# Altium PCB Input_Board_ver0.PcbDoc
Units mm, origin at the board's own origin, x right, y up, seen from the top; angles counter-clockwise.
Board outline 80 x 80 mm, 4 copper layers (Component Side, Signal Layer 1, Signal Layer 2, Bottom Layer), stack 0.651 mm thick; 143 components, 54 nets, 312 pads, 266 vias.
Unrouted connection lines stored in the file: 326.
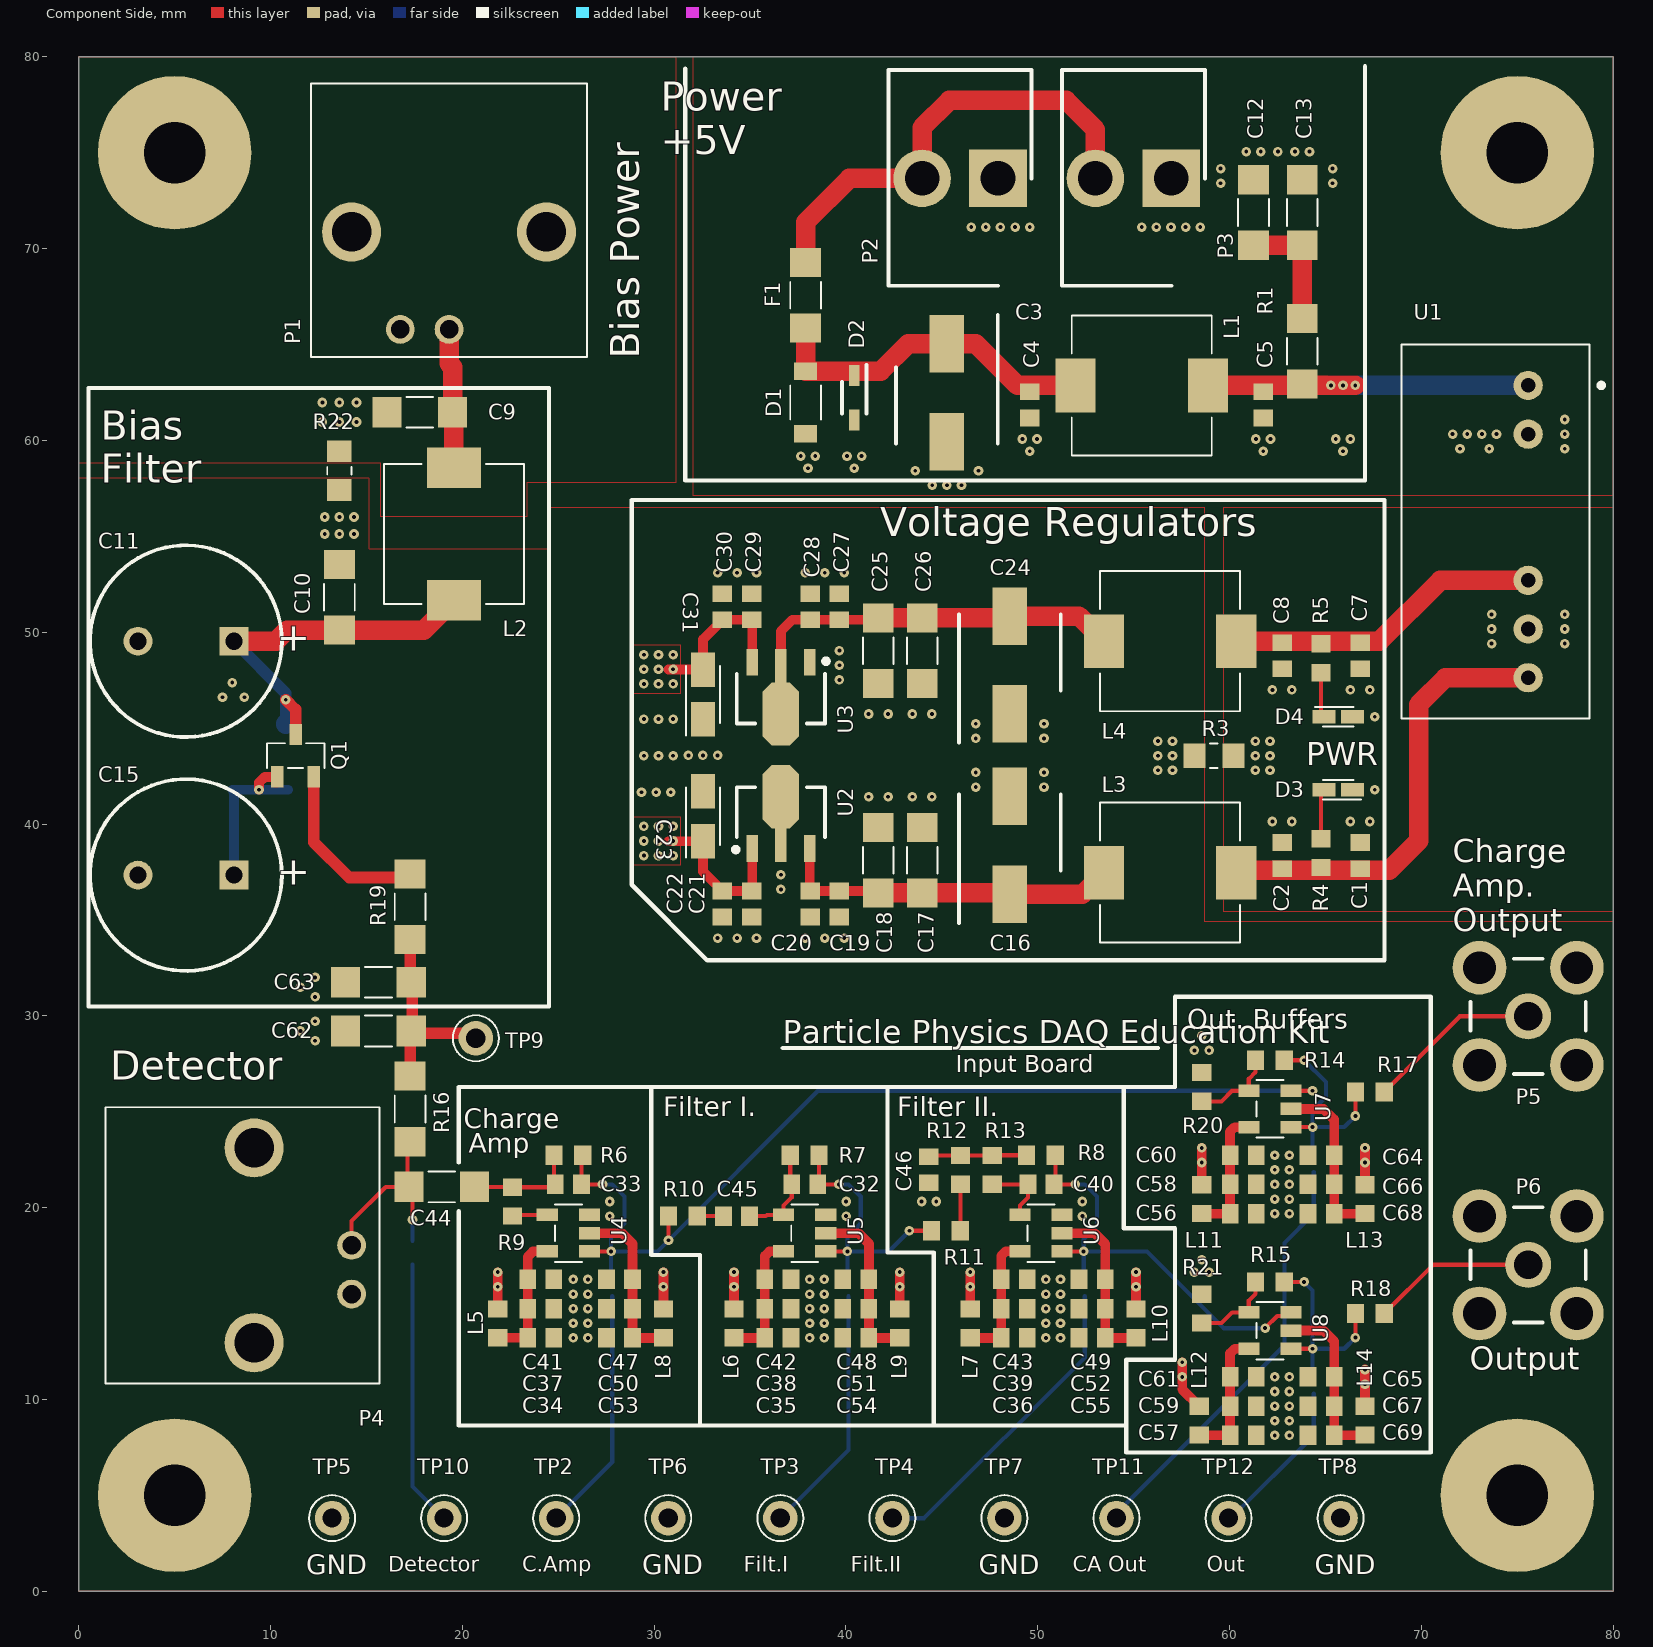
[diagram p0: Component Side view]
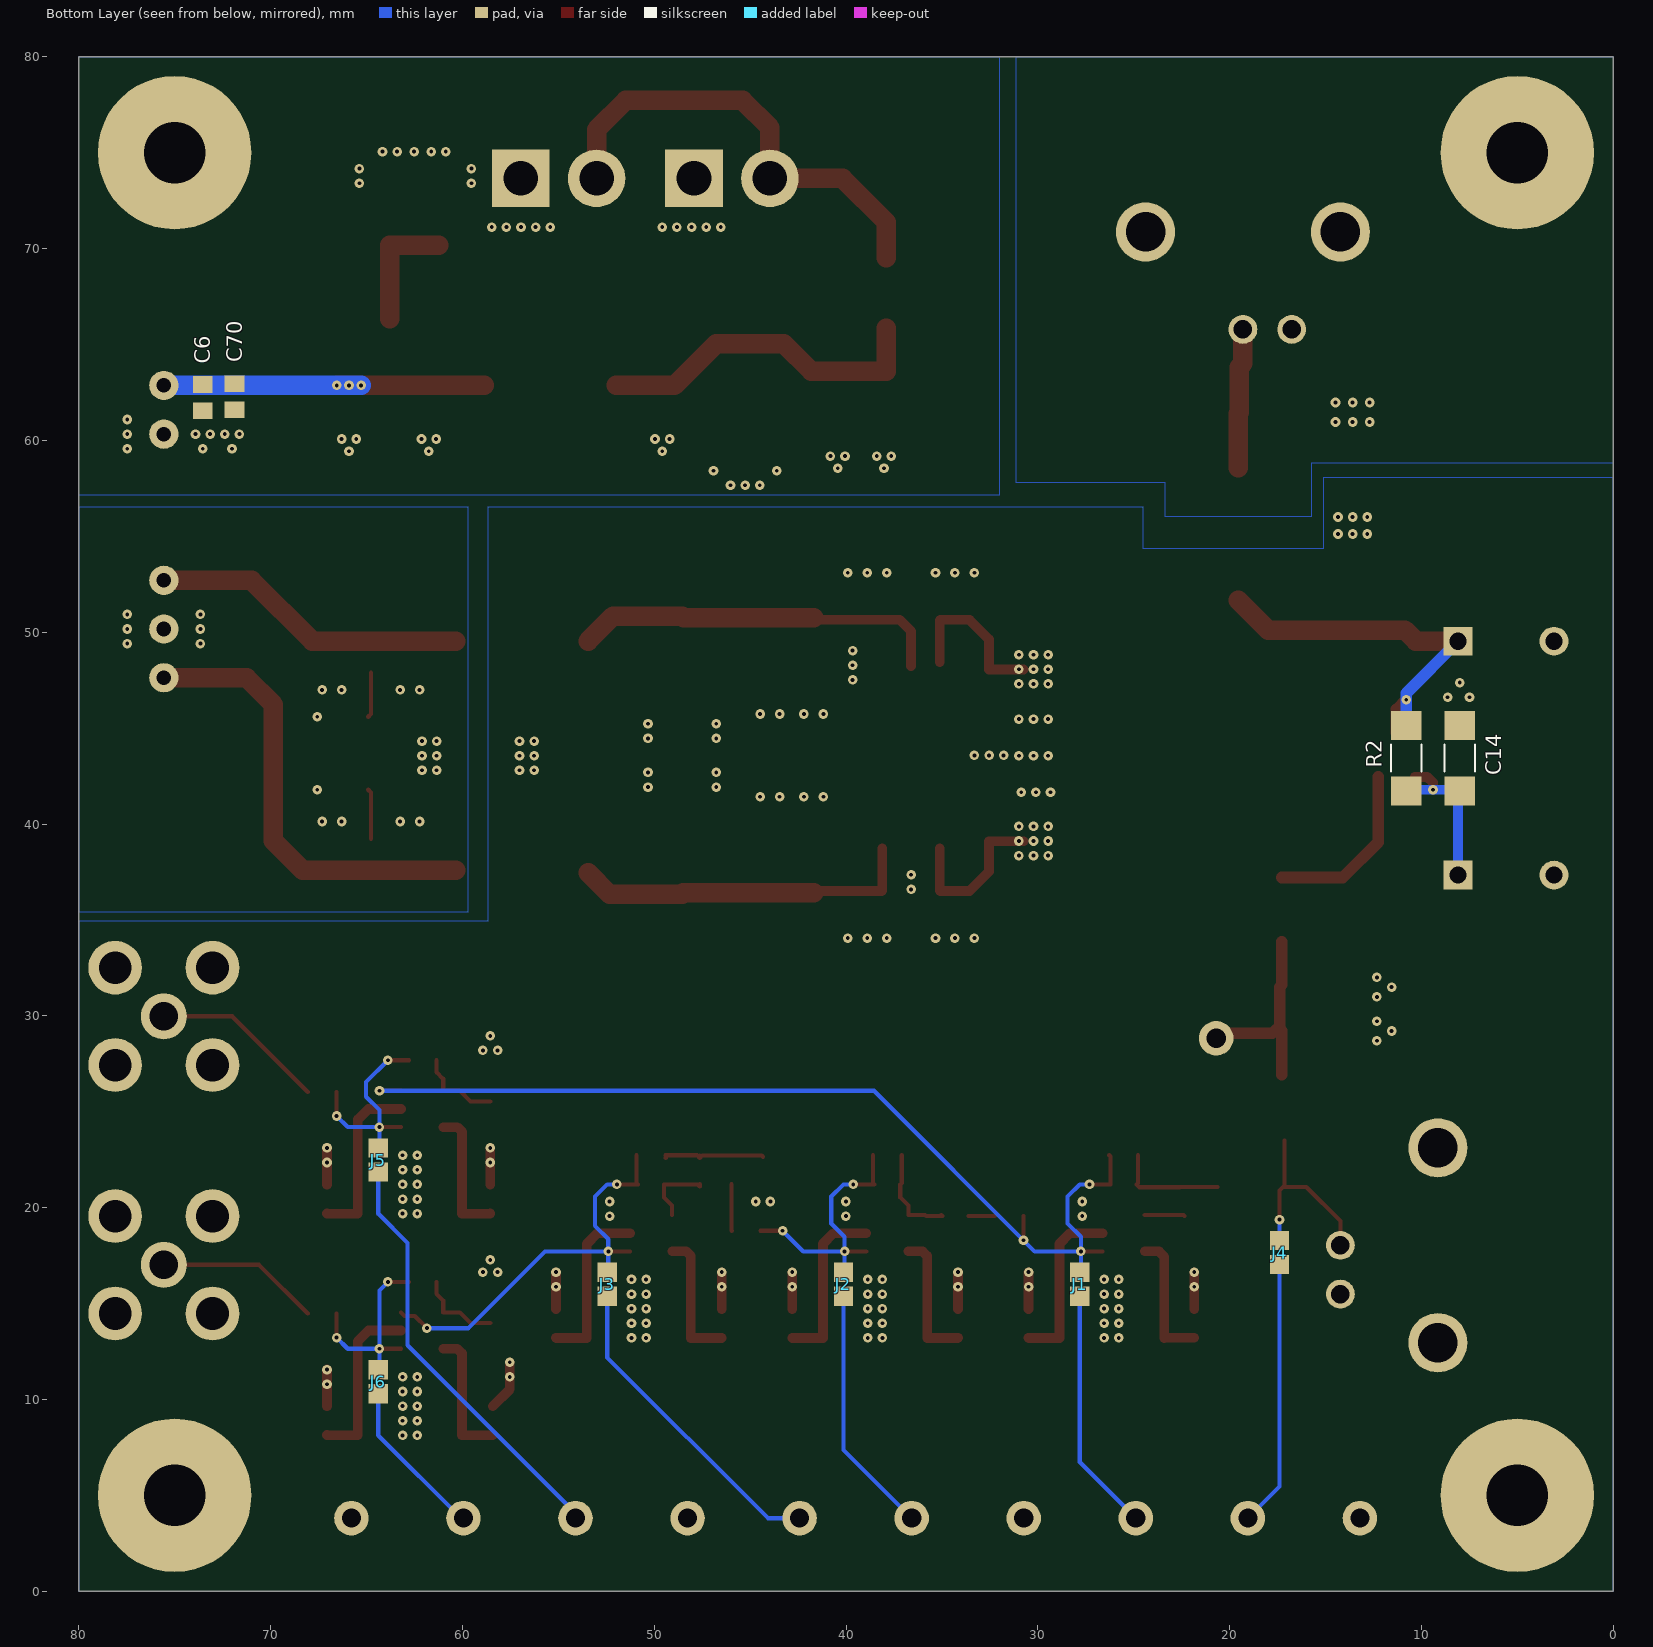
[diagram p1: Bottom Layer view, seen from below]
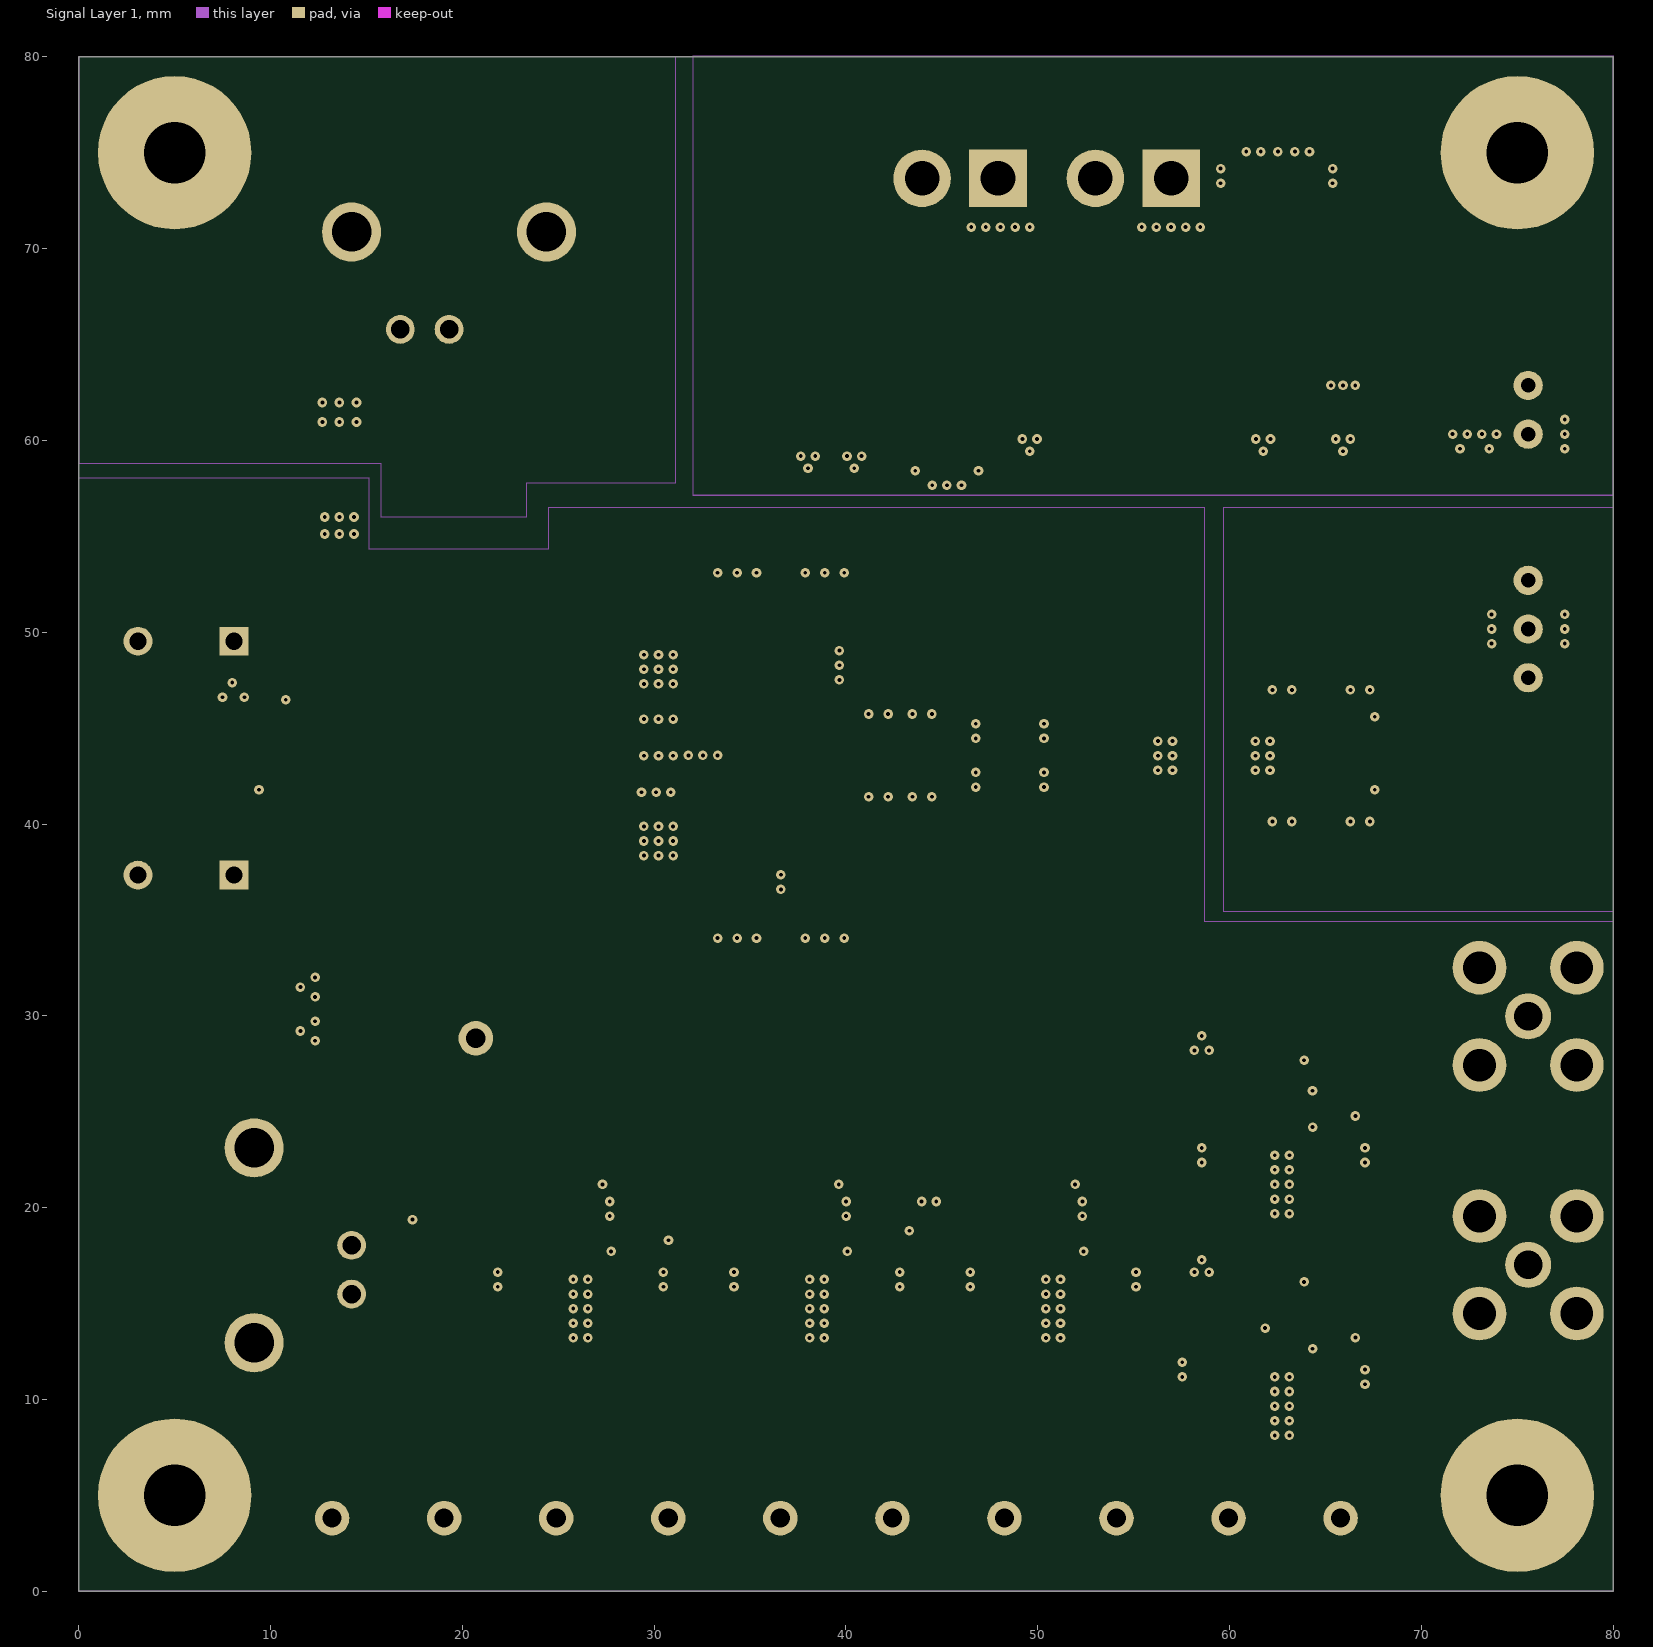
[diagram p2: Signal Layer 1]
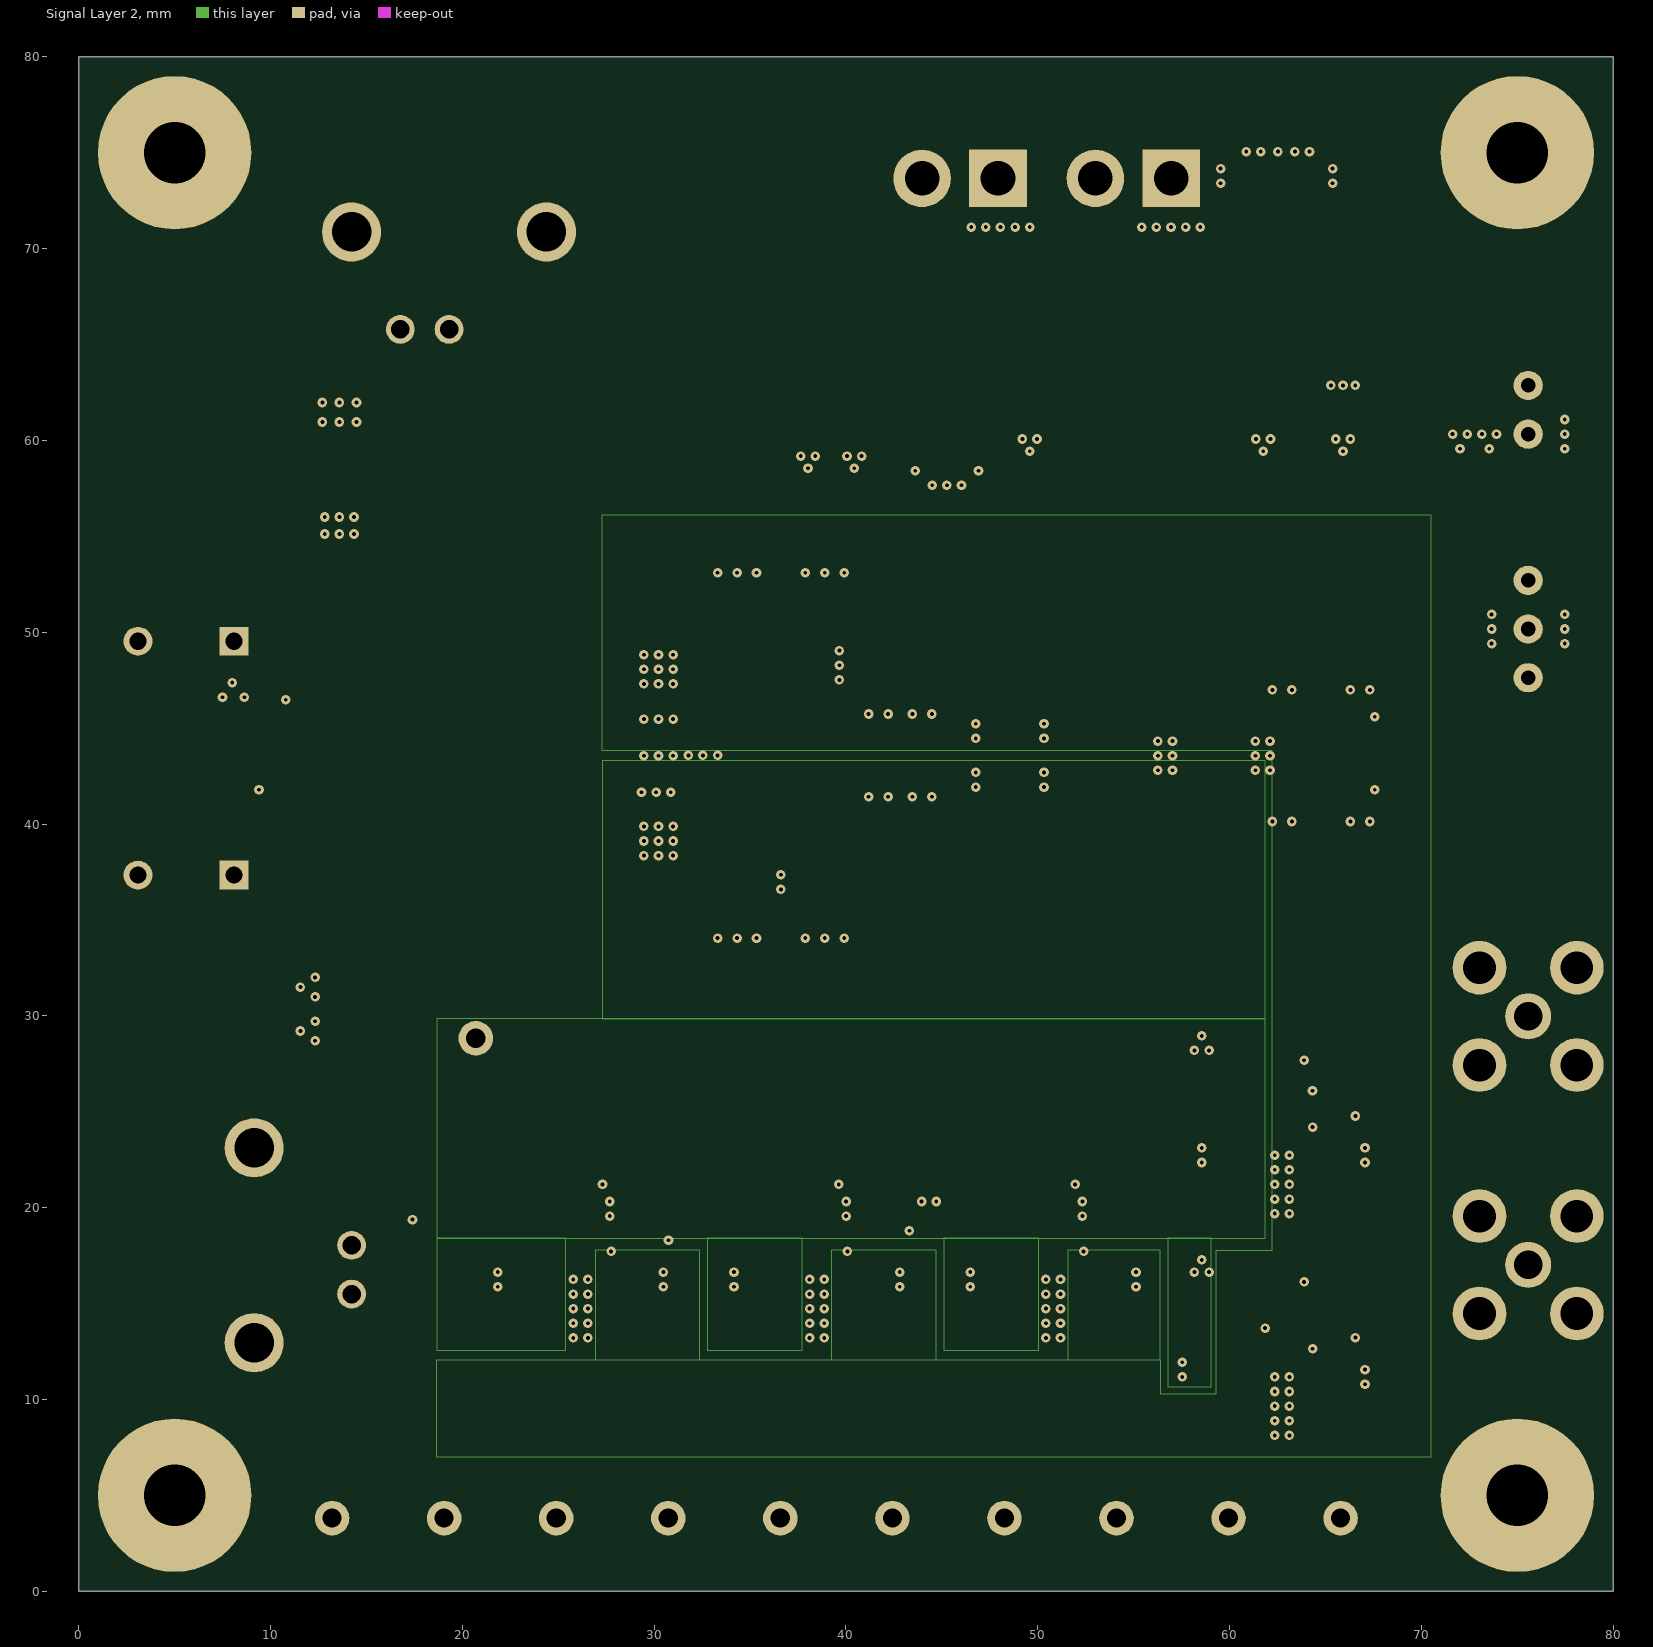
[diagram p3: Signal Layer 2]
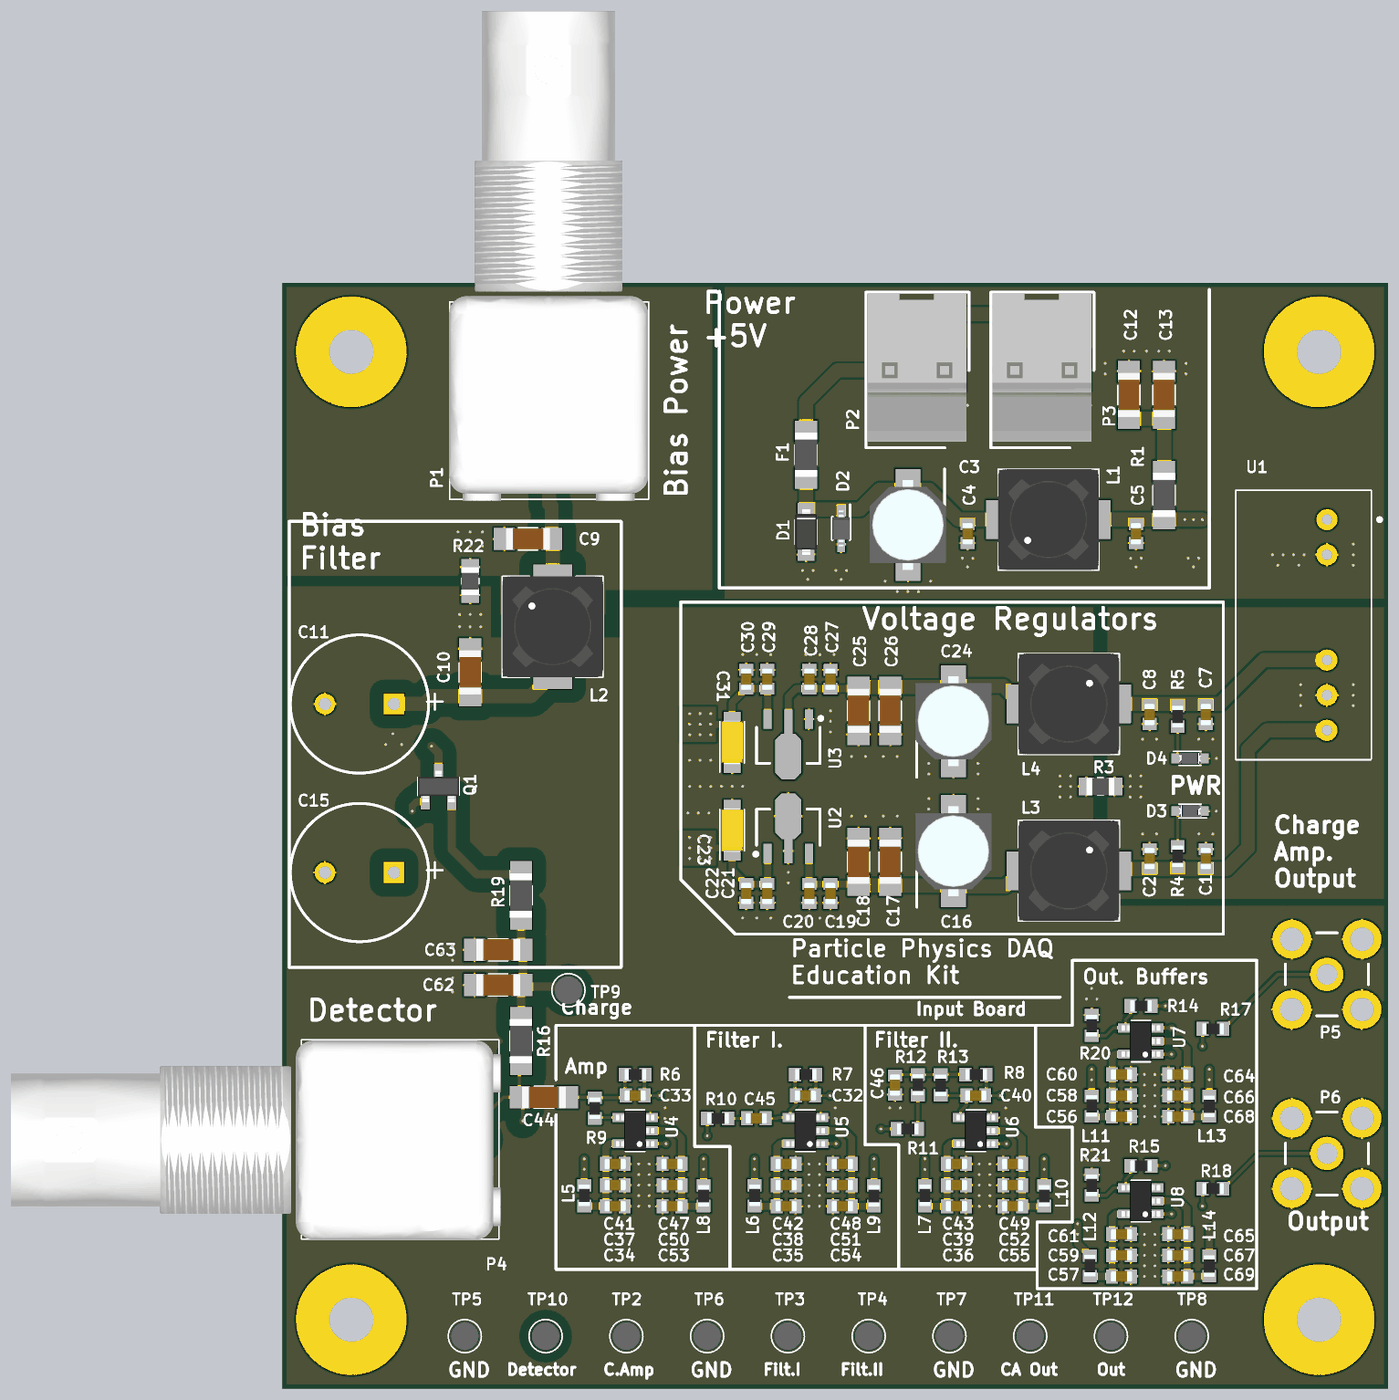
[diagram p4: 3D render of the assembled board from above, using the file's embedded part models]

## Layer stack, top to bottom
Top Solder: solder mask 0.0102, Solder Resist, Dk 3.5
Component Side: signal copper 0.0356
Dielectric 1: prepreg 0.127, FR-4, Dk 4.2
Signal Layer 1: signal copper 0.036
Dielectric 3: core 0.254, Dk 4.2
Signal Layer 2: signal copper 0.036
Dielectric 2: prepreg 0.127, Dk 4.2
Bottom Layer: signal copper 0.0356
Solder Side: solder mask 0.0102, Solder Resist, Dk 3.5

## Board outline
0,0 80,0 80,80 0,80

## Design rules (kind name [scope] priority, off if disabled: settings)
AcuteAngle [All] p1: minimum=6.00000000000000E+0001 checktracksonly=FALSE
BoardOutlineClearance [All] p1: gap=0.3 ignorepadtopadclearanceinfootprint=FALSE
Clearance "Clearance - SB" [HasFootprint('SOLDER_BRIDGE_1MM')] p1: gap=0.15 ignorepadtopadclearanceinfootprint=FALSE except(0: Arc-Hole Track-Hole SMDPad-Hole THPad-Hole Via-Hole Fill-Hole Poly-Hole Region-Hole Text-Hole)
Clearance Clearance_HV [InNetClass('HV')] p2: gap=1 ignorepadtopadclearanceinfootprint=FALSE except(0: Arc-Hole Track-Hole SMDPad-Hole THPad-Hole Via-Hole Fill-Hole Poly-Hole Region-Hole Text-Hole)
Clearance [All] p3: gap=0.15 ignorepadtopadclearanceinfootprint=FALSE except(0: Arc-Hole Track-Hole SMDPad-Hole THPad-Hole Via-Hole Fill-Hole Poly-Hole Region-Hole Text-Hole)
Height [All] p1: minheight=0 maxheight=50 prefheight=12.7
HoleSize [All] p1: absolutevalues=TRUE maxlimit=4 minlimit=0.2 maxpercent=80.000 minpercent=20.000
MinimumSolderMaskSliver [All] p1: minsoldermaskwidth=0.065
PolygonConnect [All] p1: thpad.connectstyle=Relief thpad.reliefconductorwidth=0.15 thpad.reliefentries=4 thpad.polygonreliefangle="90 Angle" thpad.airgapwidth=0.15 smdpad.connectstyle=Relief smdpad.reliefconductorwidth=0.15 smdpad.reliefentries=4 smdpad.polygonreliefangle="90 Angle" smdpad.airgapwidth=0.15 via.connectstyle=Direct via.reliefconductorwidth=0.254 via.reliefentries=4 via.polygonreliefangle="90 Angle" via.airgapwidth=0.254
RoutingVias [All] p1: holewidth=0.2 width=0.5 viastyle="Through Hole" minholewidth=0.2 minwidth=0.5 maxholewidth=0.2 maxwidth=0.5
SilkToSilkClearance [All] p1: silktosilkclearance=0.1
SilkToSolderMaskClearance [IsPad] p1: minsilkscreentomaskgap=0.1 clearancetoexposedcopper=TRUE
SolderMaskExpansion [All] p1: expansion=0.07
Width "Width - 50R" [InNetClass('50R')] p1: maxlimit=0.22 minlimit=0.22 preferedwidth=0.22
Width [All] p2: maxlimit=1.016 minlimit=0.15 preferedwidth=0.508
25 further rules are at their usual default settings.

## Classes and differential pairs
component class PreAmp: C32 C33 C34 C35 C36 C37 C38 C39 C40 C41 C42 C43 C44 C45 C46 C47 C48 C49 C50 C51 C52 C53 C54 C55 C56 C57 C58 C59 C60 C61 C62 C63 C64 C65 C66 C67 C68 C69 J1 J2 J3 J4 J5 J6 L5 L6 L7 L8 L9 L10 L11 L12 L13 L14 P4 P5 P6 R6 R7 R8 R9 R10 R11 R12 R13 R14 R15 R16 R17 R18 R19 R20 R21 TP2 TP3 TP4 TP5 TP6 TP7 TP8 TP9 TP10 TP11 TP12 U4 U5 U6 U7 U8
component class Power: C1 C2 C3 C4 C5 C6 C7 C8 C9 C10 C11 C12 C13 C14 C15 C16 C17 C18 C19 C20 C21 C22 C23 C24 C25 C26 C27 C28 C29 C30 C31 C70 D1 D2 D3 D4 F1 L1 L2 L3 L4 P1 P2 P3 Q1 R1 R2 R3 R4 R5 R22 U1 U2 U3
net class HV: Diode_Bias NetC9_2 NetC10_2 NetC14_2 NetC62_2 NetJ4_1 PIN_Input
net class 50R: Amp_OUT Filter_OUT NetC32_1 NetC32_2 NetC33_1 NetJ5_2 NetJ6_2 NetP5_1 NetP6_1 NetR14_1 NetR15_1 PIN_Input

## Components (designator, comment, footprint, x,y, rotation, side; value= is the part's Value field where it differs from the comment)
C1 "100n" SMD_CAPACITOR_0603 66.802,38.354 r270 top
C2 "1u" SMD_CAPACITOR_0603 62.738,38.354 r270 top
C3 "10u" SMD_CAP_POL_D5.0mm 45.258,62.484 r270 top
C4 "100n" SMD_CAPACITOR_0603 49.576,61.849 r90 top
C5 "100n" SMD_CAPACITOR_0603 61.752,61.849 r90 top
C6 "100n" SMD_CAPACITOR_0603 73.533,62.23 r90 bottom
C7 "100n" SMD_CAPACITOR_0603 66.802,48.768 r270 top
C8 "1u" SMD_CAPACITOR_0603 62.738,48.768 r270 top
C9 "100n" SMD_CAPACITOR_1206 17.78,61.468 r0 top
C10 "100n" SMD_CAPACITOR_1206 13.589,51.816 r270 top
C11 "10u" CAPPR5-10x25 5.588,49.53 r180 top
C12 "10u" SMD_CAPACITOR_1206 61.244,71.882 r270 top
C13 "10u" SMD_CAPACITOR_1206 63.784,71.882 r270 top
C14 "100n" SMD_CAPACITOR_1206 8.001,43.434 r270 bottom
C15 "10u" CAPPR5-10x25 5.588,37.338 r180 top
C16 "10u" SMD_CAP_POL_D5.0mm 48.544,38.888 r90 top
C17 "10u" SMD_CAPACITOR_1206 43.972,38.116 r270 top
C18 "D.N.P." SMD_CAPACITOR_1206 41.686,38.116 r270 top
C19 "100n" SMD_CAPACITOR_0603 39.654,35.83 r90 top
C20 "D.N.P." SMD_CAPACITOR_0603 38.13,35.83 r90 top
C21 "D.N.P." SMD_CAPACITOR_0603 35.082,35.83 r90 top
C22 "100n" SMD_CAPACITOR_0603 33.558,35.83 r90 top
C23 "1u" SMD_CAPACITOR_POL_A_3216 32.542,40.402 r90 top
C24 "10u" SMD_CAP_POL_D5.0mm 48.544,48.286 r90 top
C25 "10u" SMD_CAPACITOR_1206 41.686,49.038 r90 top
C26 "D.N.P." SMD_CAPACITOR_1206 43.972,49.038 r90 top
C27 "100n" SMD_CAPACITOR_0603 39.654,51.324 r270 top
C28 "D.N.P." SMD_CAPACITOR_0603 38.13,51.324 r270 top
C29 "D.N.P." SMD_CAPACITOR_0603 35.082,51.324 r270 top
C30 "100n" SMD_CAPACITOR_0603 33.558,51.324 r270 top
C31 "1u" SMD_CAPACITOR_POL_A_3216 32.542,46.752 r90 top
C32 "150p" SMD_CAPACITOR_0603 37.846,21.209 r0 top
C33 "10p" SMD_CAPACITOR_0603 25.527,21.209 r0 top
C34 "D.N.P." SMD_CAPACITOR_0603 24.085,13.208 r0 top
C35 "D.N.P." SMD_CAPACITOR_0603 36.449,13.208 r0 top
C36 "D.N.P." SMD_CAPACITOR_0603 48.768,13.208 r0 top
C37 "100nF" SMD_CAPACITOR_0603 24.085,14.732 r0 top
C38 "100nF" SMD_CAPACITOR_0603 36.449,14.732 r0 top
C39 "100nF" SMD_CAPACITOR_0603 48.768,14.732 r0 top
C40 "10p" SMD_CAPACITOR_0603 50.165,21.209 r0 top
C41 "10nF" SMD_CAPACITOR_0603 24.085,16.256 r0 top
C42 "10nF" SMD_CAPACITOR_0603 36.449,16.256 r0 top
C43 "10nF" SMD_CAPACITOR_0603 48.768,16.256 r0 top
C44 "2n2" SMD_CAPACITOR_1206 18.923,21.082 r0 top
C45 "1n" SMD_CAPACITOR_0603 34.29,19.558 r0 top
C46 "330p" SMD_CAPACITOR_0603 44.323,21.971 r90 top
C47 "10nF" SMD_CAPACITOR_0603 28.194,16.256 r180 top
C48 "10nF" SMD_CAPACITOR_0603 40.513,16.256 r180 top
C49 "10nF" SMD_CAPACITOR_0603 52.832,16.256 r180 top
C50 "100nF" SMD_CAPACITOR_0603 28.194,14.732 r180 top
C51 "100nF" SMD_CAPACITOR_0603 40.513,14.732 r180 top
C52 "100nF" SMD_CAPACITOR_0603 52.832,14.732 r180 top
C53 "D.N.P." SMD_CAPACITOR_0603 28.194,13.208 r180 top
C54 "D.N.P." SMD_CAPACITOR_0603 40.513,13.208 r180 top
C55 "D.N.P." SMD_CAPACITOR_0603 52.832,13.208 r180 top
C56 "D.N.P." SMD_CAPACITOR_0603 60.706,19.685 r0 top
C57 "D.N.P." SMD_CAPACITOR_0603 60.706,8.128 r0 top
C58 "100nF" SMD_CAPACITOR_0603 60.706,21.209 r0 top
C59 "100nF" SMD_CAPACITOR_0603 60.706,9.652 r0 top
C60 "10nF" SMD_CAPACITOR_0603 60.706,22.733 r0 top
C61 "10nF" SMD_CAPACITOR_0603 60.706,11.176 r0 top
C62 "10n" SMD_CAPACITOR_1206 15.621,29.21 r0 top
C63 "100n" SMD_CAPACITOR_1206 15.621,31.75 r0 top
C64 "10nF" SMD_CAPACITOR_0603 64.77,22.733 r180 top
C65 "10nF" SMD_CAPACITOR_0603 64.77,11.176 r180 top
C66 "100nF" SMD_CAPACITOR_0603 64.77,21.209 r180 top
C67 "100nF" SMD_CAPACITOR_0603 64.77,9.652 r180 top
C68 "D.N.P." SMD_CAPACITOR_0603 64.77,19.685 r180 top
C69 "D.N.P." SMD_CAPACITOR_0603 64.77,8.128 r180 top
C70 "1u" SMD_CAPACITOR_0603 71.882,62.275 r90 bottom
D1 "1N4148W" SMD_SOD-123 37.892,61.976 r90 top
D2 "SD05.TCT" SMD_SOD-323 40.432,62.23 r270 top
D3 "GREEN" SMD_LED_0603 65.659,41.783 r180 top
D4 "GREEN" SMD_LED_0603 65.659,45.593 r0 top
F1 "Fuse" SMD_RESISTOR_1206 37.892,67.564 r270 top
J1 "SB" SOLDER_BRIDGE_1MM 27.813,16.002 r270 bottom
J2 "SB" SOLDER_BRIDGE_1MM 40.132,16.002 r270 bottom
J3 "SB" SOLDER_BRIDGE_1MM 52.451,16.002 r270 bottom
J4 "SB" SOLDER_BRIDGE_1MM 17.399,17.653 r90 bottom
J5 "SB" SOLDER_BRIDGE_1MM 64.389,22.479 r90 bottom
J6 "SB" SOLDER_BRIDGE_1MM 64.389,10.922 r90 bottom
L1 "47uH" SMD_INDUCTOR_7.3MM 55.418,62.865 r0 top
L2 "100u" SMD_INDUCTOR_7.3MM 19.558,55.118 r270 top
L3 "220uH" SMD_INDUCTOR_7.3MM 56.896,37.465 r180 top
L4 "220uH" SMD_INDUCTOR_7.3MM 56.896,49.53 r180 top
L5 "1k@100MHz" SMD_RES_0603 21.844,13.97 r90 top
L6 "1k@100MHz" SMD_RES_0603 34.163,13.97 r90 top
L7 "1k@100MHz" SMD_RES_0603 46.482,13.97 r90 top
L8 "1k@100MHz" SMD_RES_0603 30.48,13.97 r270 top
L9 "1k@100MHz" SMD_RES_0603 42.799,13.97 r270 top
L10 "1k@100MHz" SMD_RES_0603 55.118,13.97 r270 top
L11 "1k@100MHz" SMD_RES_0603 58.547,20.447 r90 top
L12 "1k@100MHz" SMD_RES_0603 58.42,8.89 r90 top
L13 "1k@100MHz" SMD_RES_0603 67.056,20.447 r270 top
L14 "1k@100MHz" SMD_RES_0603 67.056,8.89 r270 top
P1 "BNC" BNC_0315637 16.764,65.786 r0 top
P2 "09-65-2028" SHDR2W165P0X396_1X2_716X1062X1425P 56.965,73.66 r180 top
P3 "09-65-2028" SHDR2W165P0X396_1X2_716X1062X1425P 47.925,73.66 r180 top
P4 "BNC" BNC_0315637 14.224,15.494 r90 top
P5 "SMA_Female" SMA5.08-H 75.565,29.972 r180 top
P6 "SMA_Female" SMA5.08-H 75.565,17.018 r180 top
Q1 "MMBT5551" SMD_SOT-23 11.303,43.561 r0 top
R1 "6R8" SMD_RESISTOR_1206 63.784,64.643 r270 top
R2 "10k" SMD_RESISTOR_1206 10.795,43.434 r90 bottom
R3 "0" SMD_RESISTOR_0805 59.182,43.561 r180 top
R4 "1k2" SMD_RES_0603 64.77,38.481 r90 top
R5 "1k2" SMD_RES_0603 64.77,48.641 r270 top
R6 "100M" SMD_RES_0603 25.527,22.733 r0 top
R7 "2k6" SMD_RES_0603 37.846,22.733 r0 top
R8 "11k" SMD_RES_0603 50.165,22.733 r0 top
R9 "0" SMD_RES_0603 22.606,20.308 r270 top
R10 "390" SMD_RES_0603 31.496,19.558 r0 top
R11 "0" SMD_RES_0603 45.212,18.796 r0 top
R12 "910" SMD_RES_0603 45.974,21.971 r90 top
R13 "4k3" SMD_RES_0603 47.625,21.971 r270 top
R14 "D.N.P." SMD_RES_0603 62.103,27.686 r0 top
R15 "D.N.P." SMD_RES_0603 62.103,16.129 r0 top
R16 "10M" SMD_RESISTOR_1206 17.272,25.146 r90 top
R17 "49.9" SMD_RES_0603 67.31,26.035 r0 top
R18 "49.9" SMD_RES_0603 67.31,14.478 r0 top
R19 "1k" SMD_RESISTOR_1206 17.272,35.687 r90 top
R20 "0" SMD_RES_0603 58.547,26.289 r270 top
R21 "0" SMD_RES_0603 58.547,14.732 r270 top
R22 "0" SMD_RESISTOR_0805 13.589,58.42 r270 top
TP2 "Test Pin" PIn_1mm 24.892,3.81 r0 top
TP3 "Test Pin" PIn_1mm 36.576,3.81 r0 top
TP4 "Test Pin" PIn_1mm 42.418,3.81 r0 top
TP5 "Test Pin" PIn_1mm 13.208,3.81 r0 top
TP6 "Test Pin" PIn_1mm 30.734,3.81 r0 top
TP7 "Test Pin" PIn_1mm 48.26,3.81 r0 top
TP8 "Test Pin" PIn_1mm 65.786,3.81 r0 top
TP9 "Test Pin" PIn_1mm 20.701,28.829 r0 top
TP10 "Test Pin" PIn_1mm 19.05,3.81 r0 top
TP11 "Test Pin" PIn_1mm 54.102,3.81 r0 top
TP12 "Test Pin" PIn_1mm 59.944,3.81 r0 top
U1 "AM2DM - DH" AM2DM_dual_3 75.565,62.865 r270 top
U2 "L78L05ACUTR" SOT-89_N 36.606,40.618 r90 top
U3 "L79L05ACUTR" SOT-89_N 36.606,46.536 r270 top
U4 "AD8065" SMD_SOT-23-5 25.527,18.669 r90 top
U5 "AD8065" SMD_SOT-23-5 37.846,18.669 r90 top
U6 "AD8065" SMD_SOT-23-5 50.165,18.669 r90 top
U7 "MAX4014" SMD_SOT-23-5 62.103,25.146 r90 top
U8 "MAX4014" SMD_SOT-23-5 62.103,13.589 r90 top

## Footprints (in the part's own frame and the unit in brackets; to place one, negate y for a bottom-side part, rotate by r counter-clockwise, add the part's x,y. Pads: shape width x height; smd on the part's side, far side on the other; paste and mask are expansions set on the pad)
AM2DM_dual_3 [mil]
  round 60 hole 30: 1(0,0) 2(100,0) 5(400,0) 6(500,0) 7(600,0)
  silkscreen extent -84,-260 684,155, body extent -84,-260 684,126, height 492
BNC_0315637 [mm]
  round 1.501 hole 0.965: 1(0,0) 2(2.54,0)
  round 3.085 hole 2.057: MH1(-2.54,5.08) MH2(7.62,5.08)
  silkscreen extent -4.66,-1.45 9.74,12.83, body extent -4.7,-1.56 9.7,33.85, height 12.98
CAPPR5-10x25 [mm] "Capacitor, Electrolytic, Radial; Body 10 x 25 mm (Dia.xH typ); Pin Spacing 5 mm (typ)"
  rect 1.5x1.5 hole 0.9: 1(-2.5,0)
  round 1.5 hole 0.9: 2(2.5,0)
  silkscreen extent -5,-5 5,5
PIn_1mm [mm]
  round 1.8 hole 1: 1(0,0)
  silkscreen extent -1.2,-1.2 1.2,1.2, body extent -1,-1 1,1, height 4.6
SHDR2W165P0X396_1X2_716X1062X1425P [mm]
  rect 3x3 hole 1.8: 1(0,0)
  round 3 hole 1.8: 2(3.96,0)
  silkscreen extent -1.75,-5.65 5.71,5.6, body extent -1.58,-5.6 5.58,5.15, height 13.85
SMA5.08-H [mm] "Connector; RF Coaxial, MCX, Thru-Hole; 5 Position; Right Angle"
  round 2.4 hole 1.5: 1(0,0)
  round 2.8 hole 1.7: 2(-2.54,-2.54) 3(2.54,-2.54) 4(2.54,2.54) 5(-2.54,2.54)
  silkscreen extent -3,-3 3,3, body extent -6.5,-3 3,3, height 5.99
SMD_CAP_POL_D5.0mm [mm]
  rect 3x1.8 smd: 1(-2.55,0) 2(2.55,0)
  silkscreen extent -4.05,-2.65 2.65,2.65, body extent -3.25,-2.75 3.25,2.75, height 6.1
SMD_CAPACITOR_0603 [mm]
  rect 0.87x1.02 smd: 1(-0.68,0) 2(0.68,0)
  body extent -0.8,-0.4 0.8,0.4, height 1
SMD_CAPACITOR_1206 [mm]
  rect 1.52x1.6 smd: 1(-1.71,0) 2(1.71,0)
  silkscreen extent -0.7,-0.8 0.7,0.8, body extent -1.6,-0.8 1.6,0.8, height 1.58
SMD_CAPACITOR_POL_A_3216 [mm]
  rect 1.8x1.25 smd: 1(-1.3,0) 2(1.3,0)
  silkscreen extent -2.15,-0.89 1.5,0.89, body extent -1.6,-0.8 1.6,0.8, height 1.8
SMD_INDUCTOR_7.3MM [mm]
  rect 2.1x2.8 smd: 1(-3.45,0) 2(3.45,0)
  silkscreen extent -3.65,-3.65 3.65,3.65, body extent -3.65,-3.65 3.65,3.65, height 4
SMD_LED_0603 [mm]
  rect 1.2x0.7 smd: 1(0.75,0) 2(-0.75,0)
  silkscreen extent -1.2,-0.51 0.8,0.51, body extent -0.8,-0.4 0.8,0.4, height 0.36
SMD_RES_0603 [mm]
  rect 0.9x1 smd: 1(-0.75,0) 2(0.75,0)
  body extent -0.75,-0.4 0.8,0.4, height 0.55
SMD_RESISTOR_0805 [mm]
  rect 1.14x1.27 smd: 1(-1.015,0) 2(1.015,0)
  silkscreen extent -0.2,-0.64 0.2,0.64, body extent -1,-0.64 1,0.64, height 0.61
SMD_RESISTOR_1206 [mm]
  rect 1.52x1.6 smd: 1(-1.71,0) 2(1.71,0)
  silkscreen extent -0.7,-0.8 0.7,0.8, body extent -1.6,-0.81 1.6,0.81, height 0.61
SMD_SOD-123 [mm]
  rect 0.91x1.2 smd: 1(-1.635,0) 2(1.635,0)
  silkscreen extent -0.9,-0.8 0.9,0.8, body extent -1.65,-0.8 1.65,0.8, height 1.2
SMD_SOD-323 [mm]
  rect 1.088x0.55 smd: 1(1.158,0) 2(-1.158,0)
  silkscreen extent -1.7,-0.64 0.82,0.64, body extent -1.29,-0.64 1.3,0.64, height 1.17
SMD_SOT-23 [mm]
  rect 0.65x1.1 smd: 1(-0.95,-1.1) 2(0.95,-1.1) 3(0,1.1)
  silkscreen extent -1.5,-0.65 1.5,0.65, body extent -1.5,-1.13 1.5,1.13, height 1.22
SMD_SOT-23-5 [mm]
  rect 0.65x1.1 smd: 1(-0.95,-1.1) 2(0,-1.1) 3(0.95,-1.1) 4(0.95,1.1) 5(-0.95,1.1)
  silkscreen extent -1.5,-0.7 1.5,0.7, body extent -1.45,-1.4 1.45,1.4, height 1.45
SOLDER_BRIDGE_1MM [mm]
  rect 1x1 smd: 1(-0.625,0) 2(0.625,0)
SOT-89_N [mm] "SOT89, 3-Leads, Body 4.5x2.4 mm, Pitch 1.5mm, Lead Span 4.1mm, IPC Medium Density"
  rect 1.4x0.6 smd: 1(-1.9,1.5) 3(-1.9,-1.5)
  rect 1.8x0.6 smd: 2(-1.7,0)
  oct 3.3x1.9 smd: 2(0.8,0)
  silkscreen extent -2.07,-2.3 1.3,2.47, body extent -1.3,-2.3 1.3,2.3, height 1.6

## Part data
C1 C2 C4 C5 C6 C7 C8 C9 C10 C12 C13 C14 C17 C18 C19 C20 C21 C22 C25 C26 C27 C28 C29 C30 C32 C33 C34 C35 C36 C37 C38 C39 C40 C41 C42 C43 C44 C45 C46 C47 C48 C49 C50 C51 C52 C53 C54 C55 C56 C57 C58 C59 C60 C61 C62 C63 C64 C65 C66 C67 C68 C69 C70: library part Capacitor
C3 C11 C15 C16 C23 C24 C31: library part Capacitor_pol
D1: library part Diode
D2: library part TVS_Diode_unidirect
D3 D4: library part LED
J1 J2 J3 J4 J5 J6: library part Solder_Bridge_1mm
L1 L2 L3 L4: library part Inductor
L5 L6 L7 L8 L9 L10 L11 L12 L13 L14: library part EMI_Ferrite_bead
P2 P3: "Connector", Manufacturer_Name=Molex, Mouser Part Number=538-09-65-2028, RS Part Number=6705237P
Q1: library part Transistor_NPN
R1 R2 R3 R4 R5 R6 R7 R8 R9 R10 R11 R12 R13 R14 R15 R16 R17 R18 R19 R20 R21 R22: library part Resistor
TP2 TP3 TP4 TP5 TP6 TP7 TP8 TP9 TP10 TP11 TP12: "Connector", Manufacturer_Name=Oxley, Manufacturer_Part_Number=050/LT/B2, RS Part Number=0434138

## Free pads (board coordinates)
  round 8 hole 3.2: 2(5,5) 2(5,75) 2(75,5) 2(75,75)

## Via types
v1: diameter 0.5, hole 0.2, Component Side to Bottom Layer, 266 vias

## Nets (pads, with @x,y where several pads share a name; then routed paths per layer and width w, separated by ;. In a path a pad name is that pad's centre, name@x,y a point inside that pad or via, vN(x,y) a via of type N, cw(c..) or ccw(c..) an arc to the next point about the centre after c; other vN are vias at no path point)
+5V-A: C21.2 C22.2 C23.1 L5.2 L6.2 L7.2 L11.2 L12.2 U2.1 | length 18.9
  Component Side w0.508: L5.2 v1(21.844,15.875) v1(21.844,16.637) ; v1@30.748,39.102 C23.1 32.542,37.526 C22.2 C21.2 35.106,36.534 U2.1 ; L6.2 v1(34.163,15.875) v1(34.163,16.637) ; L7.2 v1(46.482,15.875) v1(46.482,16.637) ; v1(57.531,11.938) v1(57.531,11.176) 57.531,10.529 L12.2 ; L11.2 v1(58.547,22.352) v1(58.547,23.114)
  other v1: 29.464,38.354 30.226,38.354 30.988,38.354 29.464,39.116 30.226,39.116 30.988,39.116 29.464,39.878 30.226,39.878 30.988,39.878
-5V-A: C29.2 C30.2 C31.2 L8.1 L9.1 L10.1 L13.1 L14.1 U3.3 | length 18.1
  Component Side w0.508: L8.1 v1(30.48,15.875) v1(30.48,16.637) ; v1@30.748,48.052 C31.2 32.542,49.628 C30.2 C29.2 35.106,50.62 U3.3 ; L9.1 v1(42.799,15.875) v1(42.799,16.637) ; L10.1 v1(55.118,15.875) v1(55.118,16.637) ; L14.1 v1(67.056,10.795) v1(67.056,11.557) ; L13.1 v1(67.056,22.352) v1(67.056,23.114)
  other v1: 29.464,47.304 30.226,47.304 30.988,47.304 29.464,48.066 30.226,48.066 30.988,48.066 29.464,48.828 30.226,48.828 30.988,48.828
AGND: C10.1 C11.2 C14.1 C15.2 C16.2 C17.1 C18.1 C19.1 C20.1 C21.1 C22.1 C23.2 C24.1 C25.1 C26.1 C27.1 C28.1 C29.1 C30.1 C31.1 C34.2 C35.2 C36.2 C37.2 C38.2 C39.2 C41.2 C42.2 C43.2 C46.1 C47.2 C48.2 C49.2 C50.2 C51.2 C52.2 C53.2 C54.2 C55.2 C56.2 C57.2 C58.2 C59.2 C60.2 C61.2 C62.1 C63.1 C64.2 C65.2 C66.2 C67.2 C68.2 C69.2 P4.1 P5.2 P5.3 P5.4 P5.5 P6.2 P6.3 P6.4 P6.5 R3.2 R20.1 R21.1 R22.2 TP5.1 TP6.1 TP7.1 TP8.1 U2.2 U3.1 U4.3 U5.3 U6.3
  other v1: 62.357,8.128 63.119,8.128 62.357,8.89 63.119,8.89 62.357,9.652 63.119,9.652 62.357,10.414 63.119,10.414 62.357,11.176 63.119,11.176 25.781,13.208 26.543,13.208 38.1,13.208 38.862,13.208 50.419,13.208 51.181,13.208 25.781,13.97 26.543,13.97 38.1,13.97 38.862,13.97 50.419,13.97 51.181,13.97 25.781,14.732 26.543,14.732 38.1,14.732 38.862,14.732 50.419,14.732 51.181,14.732 25.781,15.494 26.543,15.494 38.1,15.494 38.862,15.494 50.419,15.494 51.181,15.494 25.781,16.256 26.543,16.256 38.1,16.256 38.862,16.256 50.419,16.256 51.181,16.256 58.166,16.637 58.928,16.637 58.547,17.272 27.686,19.558 40.005,19.558 52.324,19.558 62.357,19.685 63.119,19.685 27.686,20.32 40.005,20.32 43.942,20.32 44.704,20.32 52.324,20.32 62.357,20.447 63.119,20.447 62.357,21.209 63.119,21.209 62.357,21.971 63.119,21.971 62.357,22.733 63.119,22.733 58.166,28.194 58.928,28.194 12.319,28.702 58.547,28.956 11.557,29.21 12.319,29.718 12.319,30.988 11.557,31.496 12.319,32.004 33.304,34.052 34.32,34.052 35.336,34.052 37.876,34.052 38.892,34.052 39.908,34.052 36.606,36.592 36.606,37.354 41.178,41.418 42.194,41.418 43.464,41.418 44.48,41.418 29.337,41.656 30.099,41.656 30.861,41.656 46.766,41.926 50.322,41.926 46.766,42.688 50.322,42.688 56.261,42.799 57.023,42.799 29.464,43.561 30.226,43.561 30.988,43.561 56.261,43.561 57.023,43.561 31.78,43.577 32.542,43.577 33.304,43.577 56.261,44.323 57.023,44.323 46.766,44.466 50.322,44.466 46.766,45.228 50.322,45.228 29.464,45.466 30.226,45.466 30.988,45.466 41.178,45.736 42.194,45.736 43.464,45.736 44.48,45.736 7.493,46.609 8.636,46.609 8.001,47.371 39.654,47.514 39.654,48.276 39.654,49.038 33.304,53.102 34.32,53.102 35.336,53.102 37.876,53.102 38.892,53.102 39.908,53.102 12.827,55.118 13.589,55.118 14.351,55.118 12.827,56.007 13.589,56.007 14.351,56.007
Amp_OUT: C33.2 J1.1 R6.2 R10.1 U4.1 U7.3 | length 51.8
  Component Side w0.22: R6.2 26.207,22.663 C33.2 v1(27.305,21.209) ; U4.1 v1(27.752,17.719) ; v1(30.746,18.3) R10.1 ; U7.3 v1(64.323,26.096)
  Bottom Layer w0.22: v1(27.305,21.209) 27.813,21.209 28.448,20.574 28.448,19.177 27.752,18.481 v1(27.752,17.719) ; J1.1@27.752,16.703 v1(27.752,17.719) ; v1(64.323,26.096) 38.542,26.096 30.165,17.719 v1(27.752,17.719)
BGND: C9.1 P1.1 R22.1
  other v1: 12.7,60.96 13.589,60.96 14.478,60.96 12.7,61.976 13.589,61.976 14.478,61.976
Diode_Bias: Q1.2 R19.2 | length 9.2
  Component Side w0.6: Q1.2 12.253,39.055 14.097,37.211 R19.2@17.272,37.211
Filter_OUT: C40.2 J3.1 R8.2 U6.1 U8.3 | length 22.2
  Component Side w0.22: R8.2 50.915,21.279 C40.2 v1(51.943,21.209) ; U6.1 v1(52.39,17.719) ; v1(61.849,13.716) 62.485,14.352 63.016,14.352 U8.3
  Bottom Layer w0.22: v1(51.943,21.209) 52.451,21.209 53.086,20.574 53.086,19.05 52.39,18.354 v1(52.39,17.719) ; J3.1@52.451,16.637 52.39,16.698 v1(52.39,17.719) ; v1(61.849,13.716) 59.69,13.716 55.687,17.719 v1(52.39,17.719)
GND: C1.1 C2.1 C7.2 C8.2 D3.2 D4.1 R3.1 U1.6
  other v1: 62.23,40.132 63.246,40.132 66.294,40.132 67.31,40.132 67.564,41.783 61.341,42.799 62.103,42.799 61.341,43.561 62.103,43.561 61.341,44.323 62.103,44.323 67.564,45.593 62.23,46.99 63.246,46.99 66.294,46.99 67.31,46.99 73.66,49.403 77.47,49.403 73.66,50.165 77.47,50.165 73.66,50.927 77.47,50.927
IGND: C3.2 C4.1 C5.1 C6.1 C12.1 C13.1 C70.1 D1.1 D2.1 P2.1 P3.1 U1.2
  other v1: 44.496,57.658 45.258,57.658 46.02,57.658 43.607,58.42 46.909,58.42 38.019,58.547 40.432,58.547 37.638,59.182 38.4,59.182 40.051,59.182 40.813,59.182 49.576,59.436 61.752,59.436 65.913,59.436 72.009,59.563 73.533,59.563 77.47,59.563 49.195,60.071 49.957,60.071 61.371,60.071 62.133,60.071 65.532,60.071 66.294,60.071 71.628,60.325 72.39,60.325 73.152,60.325 73.914,60.325 77.47,60.325 77.47,61.087 46.528,71.12 47.29,71.12 48.052,71.12 48.814,71.12 49.576,71.12 55.418,71.12 56.18,71.12 56.942,71.12 57.704,71.12 58.466,71.12 59.53,73.406 65.372,73.406 59.53,74.168 65.372,74.168 60.863,75.057 61.625,75.057 62.514,75.057 63.403,75.057 64.165,75.057
NetC3_1: C3.1 C4.2 D1.2 D2.2 F1.2 L1.1 | length 17.8
  Component Side w1.016: F1.2 D1.2 41.813,63.611 43.236,65.034 C3.1 46.772,65.034 48.941,62.865 L1.1
NetC5_2: C5.2 C6.2 C70.2 L1.2 R1.2 U1.1 | length 18
  Component Side w1.016: L1.2 63.478,62.865 v1(65.278,62.865) v1(65.913,62.865) v1(66.548,62.865)
  Bottom Layer w1.016: v1(65.278,62.865) v1(65.913,62.865) v1(66.548,62.865) U1.1
NetC9_2: C9.2 L2.1 P1.2 | length 7.3
  Component Side w1.016: P1.2 19.304,64.008 19.49,63.822 C9.2 19.558,61.4 L2.1
NetC10_2: C10.2 C11.1 L2.2 Q1.3 R2.2 | length 19.7
  Component Side w0.6: v1(10.795,46.482) 11.303,45.974 Q1.3@11.303,44.75
  Component Side w1.016: C11.1 10.287,49.53 10.863,50.106 C10.2 17.996,50.106 L2.2
  Bottom Layer w0.6: C11.1 10.795,46.823 R2.2@10.795,45.216 ; R2.2@10.793,45.214 R2.2@10.795,45.216 ; R2.2@10.795,45.212 R2.2@10.795,45.216
  Bottom Layer w1.016: R2.2@10.793,45.214 R2.2@10.795,45.212
NetC12_2: C12.2 C13.2 R1.1 | length 6.4
  Component Side w1.016: C12.2 C13.2 R1.1
NetC14_2: C14.2 C15.1 Q1.1 R2.1 | length 9.2
  Component Side w0.508: v1(9.398,41.783) 9.398,42.159 9.696,42.457 10.349,42.457 Q1.1 10.353,42.236 Q1.1@10.282,42.165
  Bottom Layer w0.508: C15.1 8.088,41.696 8.001,41.783 v1(9.398,41.783) R2.1@10.922,41.783
NetC16_1: C16.1 C17.2 C18.2 C19.2 C20.2 L3.2 U2.3 | length 18.1
  Component Side w0.508: U2.3 38.106,36.534 C20.2 C19.2 41.582,36.51 C18.2
  Component Side w1.016: C18.2 C17.2 48.476,36.406 C16.1 52.319,36.338 L3.2
NetC24_2: C24.2 C25.2 C26.2 C27.2 C28.2 L4.2 U3.2 | length 19.5
  Component Side w0.508: U3.2@36.606,48.236 36.606,50.054 37.196,50.644 C28.2 C27.2 41.582,50.644 C25.2
  Component Side w1.016: C25.2 C26.2 48.456,50.748 C24.2 52.14,50.836 L4.2
NetC32_1: C32.1 C45.2 R7.1 U5.4 | length 5.2
  Component Side w0.22: C45.2@35.031,19.619 C45.2 35.814,19.558 35.875,19.619 U5.4 36.746,20.109 37.166,20.529 C32.1 37.096,21.279 R7.1
NetC32_2: C32.2 J2.1 R7.2 R11.1 U5.1 | length 14.3
  Component Side w0.22: R7.2 38.596,21.279 C32.2 v1(39.624,21.209) ; U5.1 v1(40.071,17.719) ; v1(43.307,18.796) R11.1
  Bottom Layer w0.22: v1(39.624,21.209) 40.132,21.209 40.767,20.574 40.767,19.177 40.071,18.481 v1(40.071,17.719) ; J2.1@40.132,16.637 40.071,16.698 v1(40.071,17.719) ; v1(43.307,18.796) 42.23,17.719 v1(40.071,17.719)
NetC33_1: C33.1 C44.2 R6.1 R9.1 | length 5.8
  Component Side w0.22: C44.2 22.582,21.082 R9.1 24.696,21.058 C33.1 24.777,21.279 R6.1
NetC34_1: C34.1 C37.1 C41.1 L5.1 U4.5 | length 6.9
  Component Side w0.508: L5.1 23.393,13.22 C34.1 C37.1 C41.1 23.405,17.436 23.688,17.719 U4.5
NetC35_1: C35.1 C38.1 C42.1 L6.1 U5.5 | length 7
  Component Side w0.508: L6.1 34.175,13.208 C35.1 C38.1 C42.1 35.769,17.481 36.007,17.719 U5.5
NetC36_1: C36.1 C39.1 C43.1 L7.1 U6.5 | length 7
  Component Side w0.508: L7.1 46.494,13.208 C36.1 C39.1 C43.1 48.088,17.481 48.326,17.719 U6.5
NetC40_1: C40.1 R13.2 U6.4 | length 3.8
  Component Side w0.22: R13.2 47.625,21.094 47.74,21.209 C40.1 49.485,20.529 49.065,20.109 U6.4
NetC45_1: C45.1 R10.2 | length 1.4
  Component Side w0.22: R10.2 C45.1
NetC46_2: C46.2 R8.1 R12.2 R13.1 | length 5.3
  Component Side w0.22: C46.2 44.393,22.721 R12.2 47.498,22.721 47.625,22.594 R13.1 ; R13.1@47.688,22.658 47.764,22.733 R8.1 ; R8.1@49.403,22.594 R8.1@49.415,22.606
NetC47_1: C47.1 C50.1 C53.1 L8.2 U4.2 | length 9
  Component Side w0.508: U4.2 28.321,18.669 28.874,18.116 C47.1 C50.1 C53.1 30.468,13.208 L8.2
NetC48_1: C48.1 C51.1 C54.1 L9.2 U5.2 | length 9
  Component Side w0.508: U5.2 40.64,18.669 41.193,18.116 C48.1 C51.1 C54.1 42.787,13.208 L9.2
NetC49_1: C49.1 C52.1 C55.1 L10.2 U6.2 | length 9
  Component Side w0.508: U6.2 52.959,18.669 53.512,18.116 C49.1 C52.1 C55.1 55.106,13.208 L10.2
NetC56_1: C56.1 C58.1 C60.1 L11.1 U7.5 | length 6.8
  Component Side w0.508: L11.1 58.559,19.685 C56.1 C58.1 C60.1 60.026,23.958 60.264,24.196 U7.5
NetC57_1: C57.1 C59.1 C61.1 L12.1 U8.5 | length 7
  Component Side w0.508: L12.1 58.432,8.128 C57.1 C59.1 C61.1 60.026,12.401 60.264,12.639 U8.5
NetC62_2: C62.2 C63.2 R16.2 R19.1 TP9.1 | length 10.4
  Component Side w0.6: R16.2@17.272,26.924 17.272,29.21 17.399,29.337 17.399,31.496 17.272,31.623 R19.1@17.272,33.85 ; C62.2@17.526,29.337 17.78,29.083 20.574,29.083 TP9.1@20.701,29.21
NetC64_1: C64.1 C66.1 C68.1 L13.2 U7.2 | length 9
  Component Side w0.508: U7.2 64.897,25.146 65.45,24.593 C64.1 C66.1 C68.1 67.044,19.685 L13.2
NetC65_1: C65.1 C67.1 C69.1 L14.2 U8.2 | length 9
  Component Side w0.508: U8.2 64.897,13.589 65.45,13.036 C65.1 C67.1 C69.1 67.044,8.128 L14.2
NetD3_1: D3.1 R4.2 | length 2.6
  Component Side w0.22: R4.2 64.77,41.644 D3.1
NetD4_2: D4.2 R5.2 | length 2.4
  Component Side w0.22: R5.2 64.77,45.732 D4.2
NetF1_1: F1.1 P2.2 P3.2 | length 24.3
  Component Side w1.016: F1.1@37.892,69.528 37.892,71.374 40.178,73.66 P3.2 43.965,76.304 45.385,77.724 51.481,77.724 53.005,76.2 P2.2
NetJ1_2: J1.2 TP2.1 | length 12.8
  Bottom Layer w0.22: TP2.1 27.813,6.731 J1.2
NetJ2_2: J2.2 TP3.1 | length 13
  Bottom Layer w0.22: TP3.1 40.132,7.366 J2.2
NetJ3_2: J3.2 TP4.1 | length 16.7
  Bottom Layer w0.22: TP4.1 44.069,3.81 52.451,12.192 J3.2
NetJ4_1: J4.1 TP10.1 | length 13.9
  Bottom Layer w0.22: J4.1 17.399,5.461 TP10.1
NetJ5_1: J5.1 TP11.1 | length 22.2
  Bottom Layer w0.22: TP11.1@53.975,3.937 62.865,12.827 62.865,18.161 64.389,19.685 J5.1
NetJ5_2: J5.2 R14.2 R17.1 U7.1 | length 11.3
  Component Side w0.22: R14.2@62.783,27.686 v1(63.881,27.686) ; U7.1 v1(64.328,24.196) ; v1(66.56,24.777) R17.1
  Bottom Layer w0.22: v1(63.881,27.686) 65.024,26.543 65.024,25.781 64.328,25.085 v1(64.328,24.196) ; J5.2@64.389,23.114 64.328,23.175 v1(64.328,24.196) ; v1(66.56,24.777) 65.979,24.196 v1(64.328,24.196)
NetJ6_1: J6.1 TP12.1 | length 8.3
  Bottom Layer w0.22: TP12.1@60.071,3.81 64.389,8.128 J6.1
NetJ6_2: J6.2 R15.2 R18.1 U8.1 | length 10.7
  Component Side w0.22: R15.2@62.783,16.129 v1(63.881,16.129) ; U8.1 v1(64.328,12.639) ; v1(66.56,13.22) R18.1
  Bottom Layer w0.22: v1(63.881,16.129) 64.328,15.682 v1(64.328,12.639) ; J6.2@64.389,11.557 64.328,11.618 v1(64.328,12.639) ; v1(66.56,13.22) 65.979,12.639 v1(64.328,12.639)
NetP5_1: P5.1 R17.2 | length 8.5
  Component Side w0.22: R17.2 71.997,29.972 P5.1@74.93,29.972
NetP6_1: P6.1 R18.2 | length 7.9
  Component Side w0.22: R18.2 70.6,17.018 P6.1@74.93,17.018
NetR9_2: R9.2 U4.4 | length 2.1
  Component Side w0.22: R9.2@22.352,19.57 22.401,19.619 U4.4
NetR11_2: R11.2 R12.1 | length 2.4
  Component Side w0.22: R11.2 45.974,18.808 R12.1
NetR14_1: R14.1 R20.2 U7.4 | length 4.4
  Component Side w0.22: R20.2 59.575,25.539 60.132,26.096 U7.4 61.003,26.713 61.353,27.063 R14.1
NetR15_1: R15.1 R21.2 U8.4 | length 4.4
  Component Side w0.22: R21.2 59.575,13.982 60.132,14.539 U8.4 61.003,15.156 61.353,15.506 R15.1
PIN_Input: C44.1 J4.2 P4.2 R16.1 | length 10.4
  Component Side w0.22: P4.2 14.224,19.304 16.002,21.082 17.145,21.082 17.145,21.209 17.145,23.436 R16.1@17.145,23.495 ; C44.1 17.399,20.896 v1@17.399,19.323
  Bottom Layer w0.22: v1@17.272,19.431 17.399,19.304 J4.2
  other v1: 17.399,19.372
VCC: C1.2 C2.2 L3.1 R4.1 U1.7 | length 23.5
  Component Side w1.016: L3.1@60.346,37.592 68.326,37.592 69.85,39.116 69.85,46.228 71.247,47.625 U1.7
VDD: C7.1 C8.1 L4.1 R5.1 U1.5 | length 16.5
  Component Side w1.016: L4.1 67.818,49.53 70.993,52.705 U1.5
pads on no net: P1.MH1 P1.MH2 P4.MH1 P4.MH2

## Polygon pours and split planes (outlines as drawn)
BGND on Bottom Layer "BGND - Layer 1" (solid, remove dead copper, shelved, pour order 77): 0,58.801 15.748,58.801 15.748,56.007 23.368,56.007 23.368,57.785 31.115,57.785 31.115,80.01 0,80.01
GND on Bottom Layer "GND - Layer BOT" (solid, remove dead copper, shelved, pour order 58): 80.01,35.433 59.69,35.433 59.69,56.515 80.01,56.515
IGND on Bottom Layer "IGND - Layer BOT" (solid, remove dead copper, shelved, pour order 52): 32.004,57.15 80.01,57.15 80.01,80.01 32.004,80.01
AGND on Bottom Layer "AGND - Layer 1" (solid, remove dead copper, shelved, pour order 76): 0,58.039 15.113,58.039 15.113,54.356 24.511,54.356 24.511,56.515 58.674,56.515 58.674,34.925 80.01,34.925 80.01,0 0,0
IGND on Signal Layer 1 "IGND - Layer 1" (solid, remove dead copper, shelved, pour order 75): 32.014,57.16 80.02,57.16 80.02,80.02 32.014,80.02
BGND on Signal Layer 1 "BGND - Layer 1" (solid, remove dead copper, shelved, pour order 74): 0,58.801 15.748,58.801 15.748,56.007 23.368,56.007 23.368,57.785 31.115,57.785 31.115,80.01 0,80.01
IGND on Signal Layer 1 "IGND - Layer 1" (solid, remove dead copper, shelved, pour order 48): 32.004,57.15 80.01,57.15 80.01,80.01 32.004,80.01
GND on Signal Layer 1 "GND - Layer 1" (solid, remove dead copper, shelved, pour order 46): 59.69,35.433 59.69,56.515 80,56.515 80,35.433
AGND on Signal Layer 1 "AGND - Layer 1" (solid, remove dead copper, shelved, pour order 72): 0,58.039 15.113,58.039 15.113,54.356 24.511,54.356 24.511,56.515 58.674,56.515 58.674,34.925 80.01,34.925 80.01,0 0,0
BGND on Component Side "Top Layer-B_GND" (solid, remove dead copper, shelved, pour order 70): 0,80.01 31.115,80.01 31.115,57.785 23.368,57.785 23.368,56.007 15.748,56.007 15.748,58.801 0,58.801
GND on Component Side "GND - Layer TOP" (solid, remove dead copper, shelved, pour order 60): 80.01,35.433 59.69,35.433 59.69,56.515 80.01,56.515
IGND on Component Side "IGND - Layer TOP" (solid, remove dead copper, shelved, pour order 50): 32.004,57.15 80.01,57.15 80.01,80.01 32.004,80.01
+5V-A on Component Side "+5V-A" (solid, remove dead copper, shelved, pour order 28): 28.829,40.386 31.369,40.386 31.369,37.846 28.829,37.846
-5V-A on Component Side "+5V-A" (solid, remove dead copper, shelved, pour order 40): 28.829,49.336 31.369,49.336 31.369,46.796 28.829,46.796
AGND on Component Side "Top Layer-GND" (solid, remove dead copper, shelved, pour order 68): 58.674,56.515 58.674,34.925 80.01,34.925 80.01,0 0,0 0,58.039 0.635,58.039 15.113,58.039 15.113,54.356 24.511,54.356 24.511,56.515
+5V-A on Signal Layer 2 "+5V-A" (solid, remove dead copper, shelved, pour order 2): 18.669,18.415 61.849,18.415 61.849,29.845 18.669,29.845
+5V-A on Signal Layer 2 "+5V-A" (solid, remove dead copper, shelved, pour order 4): 18.669,18.415 18.669,12.573 25.4,12.573 25.4,18.415
+5V-A on Signal Layer 2 "+5V-A" (solid, remove dead copper, shelved, pour order 10): 32.766,18.415 32.766,12.573 37.719,12.573 37.719,18.415
+5V-A on Signal Layer 2 "+5V-A" (solid, remove dead copper, shelved, pour order 12): 45.085,18.415 45.085,12.573 50.038,12.573 50.038,18.415
-5V-A on Signal Layer 2 "-5V-A" (solid, remove dead copper, shelved, pour order 18): 32.385,12.065 32.385,17.78 26.924,17.78 26.924,12.065
-5V-A on Signal Layer 2 "-5V-A" (solid, remove dead copper, shelved, pour order 20): 44.704,12.065 44.704,17.78 39.243,17.78 39.243,12.065
-5V-A on Signal Layer 2 "-5V-A" (solid, remove dead copper, shelved, pour order 22): 56.388,12.065 56.388,17.78 51.562,17.78 51.562,12.065
+5V-A on Signal Layer 2 "-5V-A" (solid, remove dead copper, shelved, pour order 36): 59.055,10.668 59.055,18.415 56.769,18.415 56.769,10.668
+5V-A on Signal Layer 2 "+5V-A" (solid, remove dead copper, shelved, pour order 26): 61.849,29.845 61.849,43.307 27.305,43.307 27.305,29.845
-5V-A on Signal Layer 2 "-5V-A" (solid, remove dead copper, shelved, pour order 34): 18.669,12.065 56.388,12.065 56.388,10.287 59.309,10.287 59.309,17.78 62.23,17.78 62.23,43.815 27.305,43.815 27.305,56.134 70.485,56.134 70.485,6.985 18.669,6.985

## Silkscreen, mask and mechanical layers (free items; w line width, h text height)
Top Overlay:
  lines w0.22: 19.812,19.812 19.812,9.144 19.812,8.636 32.893,8.636 44.577,8.636 ; 19.812,22.352 19.812,26.289 19.939,26.289 29.845,26.289 ; 31.623,79.375 31.623,57.912 35.56,57.912 67.056,57.912 67.056,79.502 ; 32.385,8.636 32.385,17.526 29.845,17.526 29.845,26.289 ; 36.703,28.321 56.261,28.321 ; 44.577,9.144 44.577,8.636 ; 54.483,26.289 54.483,18.923 57.15,18.923 57.15,12.065 54.61,12.065 54.61,8.636 ; 29.845,26.289 42.164,26.289 ; 42.164,26.289 57.15,26.289 57.15,30.988 70.485,30.988 70.485,7.239 54.61,7.239 54.61,8.636 ; 42.164,26.289 42.164,17.653 44.577,17.653 44.577,8.636 ; 44.577,8.636 54.61,8.636 ; 0.508,30.48 24.511,30.48 24.511,61.341 24.511,62.738 0.508,62.738 0.508,30.48 ; 28.829,36.83 28.829,56.896 68.072,56.896 68.072,32.893 32.766,32.893 28.829,36.83
  text "Power / +5V" at 30.353,74.93 h1.5
  text "Bias Power" at 29.21,64.262 h1.5 r90
  text "Bias / Filter" at 1.143,57.785 h1.5
  text "Voltage Regulators" at 41.783,54.991 h1.5
  text "PWR" at 64.008,43.053 h1.2
  text "Charge / Amp. / Output" at 71.628,34.417 h1.2
  text "Out. Buffers" at 57.785,29.337 h1
  text "Particle Physics DAQ Education Kit" at 36.703,28.575 h1.2
  text "Input Board" at 45.72,27.051 h0.9
  text "Detector" at 1.651,26.67 h1.5
  text "Filter I." at 30.48,24.765 h1
  text "Filter II." at 42.672,24.765 h1
  text "Charge" at 20.066,24.13 h1
  text "Amp" at 20.32,22.86 h1
  text "Output" at 72.517,11.557 h1.2
  text "Detector" at 16.129,1.016 h0.8
  text "C.Amp" at 23.114,1.016 h0.8
  text "Filt.I" at 34.671,1.016 h0.8
  text "Filt.II" at 40.259,1.016 h0.8
  text "CA Out" at 51.816,1.016 h0.8
  text "Out" at 58.801,1.016 h0.8
  text "GND" at 11.862,0.889 h1
  text "GND" at 29.388,0.889 h1
  text "GND" at 46.914,0.889 h1
  text "GND" at 64.44,0.889 h1
Mechanical 1:
  lines w2.4: -1.2,12.4 -1.2,-1.2 12.4,-1.2 ; -1.2,18.5 -1.2,36.7 ; -1.2,42.5 -1.2,60.7 ; -1.2,67.6 -1.2,81.2 12.4,81.2 ; 18.5,81.2 36.7,81.2 ; 19.3,-1.2 37.5,-1.2 ; 42.5,81.2 60.7,81.2 ; 43.3,-1.2 61.5,-1.2 ; 67.6,-1.2 81.2,-1.2 81.2,12.4 ; 67.6,81.2 81.2,81.2 81.2,67.6 ; 81.2,19.3 81.2,37.5 ; 81.2,43.3 81.2,61.5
